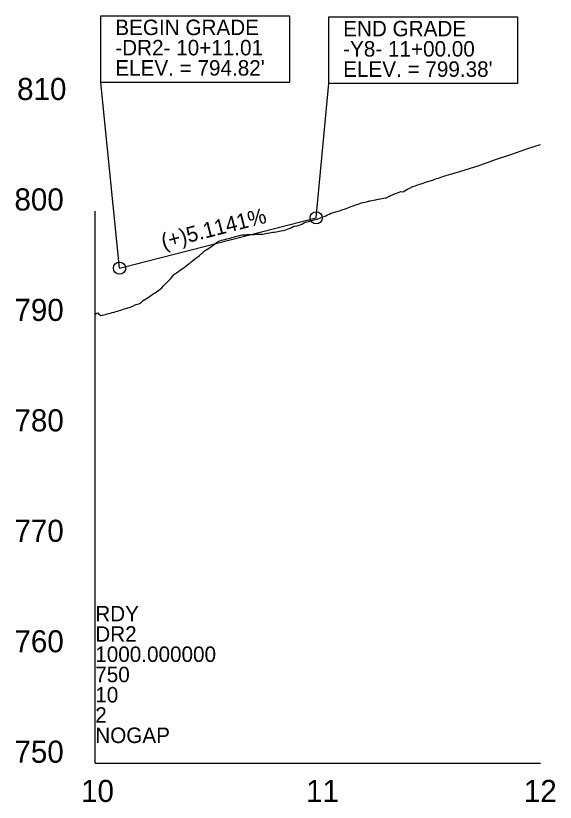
# Model space of a CAD drawing. Extents: x 579185 to 595036, y -53221 to -44640.
# Drawn here: x 593891.4 to 594135.6, y -49552.8 to -49196.7 of the extents above; entities that cross this region are included whole.
import ezdxf

# ---------------------------------------------------------------- set-up
doc = ezdxf.new("R2010")
doc.units = 0
for name, color, linetype in [('Exist Profile Cell', 7, 'Continuous'), ('Exist Vertical Profile Ground Line', 7, 'Continuous'), ('Exist Vertical Profile Horizontal Axis Label Major', 7, 'Continuous'), ('Exist Vertical Profile Vertical Axis Label', 7, 'Continuous'), ('Prop Grid Mask', 7, 'Continuous'), ('Prop Vertical Profile Curve Label', 7, 'Continuous'), ('Prop Vertical Profile Grade', 7, 'Continuous'), ('Prop Vertical Profile Grade Label', 7, 'Continuous'), ('Prop VPI Label', 7, 'Continuous')]:
    doc.layers.add(name, color=color, linetype=linetype)

msp = doc.modelspace()

# ---------------------------------------------------------------- linework, layer by layer
at = {"layer": 'Exist Profile Cell'}
for q in [(593927.42, -49285.12), (594128.93, -49535.12), (593927.42, -49535.12)]:
    msp.add_line((593927.42, -49535.12), q, dxfattribs=at)
at = {"layer": 'Exist Vertical Profile Ground Line'}
for points in [[(594073.42, -49273.27), (594074.19, -49273.01), (594074.96, -49272.76), (594075.74, -49272.49), (594076.51, -49272.23), (594077.28, -49271.98), (594078.05, -49271.73), (594078.83, -49271.48), (594079.6, -49271.24), (594080.55, -49270.96), (594081.14, -49270.74), (594081.92, -49270.46), (594082.69, -49270.19), (594083.46, -49269.93), (594084.23, -49269.67), (594084.67, -49269.52), (594085, -49269.41), (594085.78, -49269.17), (594086.55, -49268.93), (594087.32, -49268.69), (594088.09, -49268.47), (594088.87, -49268.24), (594089.64, -49268.02), (594090.41, -49267.8), (594091.18, -49267.56), (594091.96, -49267.32), (594095.23, -49266.31), (594100.76, -49264.63), (594108.55, -49261.86), (594115.49, -49259.56), (594123.25, -49256.79), (594128.93, -49255.04)], [(594001.58, -49295.59), (594002.35, -49295.56), (594003.12, -49295.53), (594003.89, -49295.5), (594004.67, -49295.35), (594005.44, -49295.15), (594006.21, -49294.98), (594006.98, -49294.86), (594007.76, -49294.75), (594008.53, -49294.63), (594009.3, -49294.5), (594010.07, -49294.37), (594010.85, -49294.24), (594011.62, -49294.12), (594012.39, -49293.99), (594013.16, -49293.86), (594013.94, -49293.53), (594014.71, -49293.21), (594015.66, -49292.81), (594016.25, -49292.54), (594017.03, -49292.2), (594017.4, -49292.04), (594017.8, -49291.95), (594018.57, -49291.77), (594019.34, -49291.6), (594019.73, -49291.52), (594020.12, -49291.34), (594020.89, -49291), (594021.66, -49290.65), (594022.58, -49290.24), (594023.21, -49290.05), (594023.98, -49289.82), (594024.75, -49289.58), (594025.52, -49289.36), (594026.3, -49289.16), (594027.07, -49288.95), (594027.84, -49288.75), (594028.61, -49288.53), (594029.39, -49288.23), (594030.16, -49287.94), (594030.93, -49287.62), (594031.7, -49287.24), (594032.48, -49286.86), (594033.25, -49286.48), (594034.08, -49286.07), (594034.79, -49285.87), (594035.57, -49285.65), (594036.34, -49285.43), (594037.27, -49285.18), (594037.88, -49284.98), (594038.66, -49284.73), (594039.43, -49284.49), (594040.2, -49284.24), (594040.97, -49283.99), (594041.75, -49283.68), (594042.52, -49283.36), (594043.29, -49283.05), (594044.06, -49282.74), (594044.54, -49282.55), (594044.84, -49282.45), (594045.61, -49282.2), (594046.38, -49281.95), (594047.15, -49281.7), (594047.45, -49281.6), (594047.93, -49281.48), (594048.7, -49281.28), (594049.47, -49281.08), (594050.24, -49280.89), (594051.02, -49280.69), (594051.44, -49280.59), (594051.79, -49280.52), (594052.56, -49280.37), (594053.33, -49280.23), (594054.11, -49280.09), (594054.43, -49280.03), (594054.88, -49279.93), (594055.65, -49279.76), (594056.42, -49279.6), (594057.2, -49279.44), (594057.97, -49279.28), (594059, -49279.08), (594059.51, -49278.85), (594060.29, -49278.51), (594061.06, -49278.17), (594062, -49277.77), (594062.6, -49277.52), (594063.38, -49277.2), (594064.15, -49276.89), (594064.92, -49276.58), (594065.69, -49276.35), (594066.75, -49276.38), (594067.24, -49276.11), (594068.01, -49275.69), (594068.78, -49275.26), (594069.56, -49274.85), (594070.33, -49274.43), (594070.74, -49274.21), (594071.1, -49274.08), (594071.87, -49273.81), (594072.65, -49273.54), (594073.42, -49273.27)], [(593927.42, -49331.74), (593928.19, -49331.39), (593928.51, -49331.24), (593928.96, -49331.63), (593929.93, -49332.46), (593930.51, -49332.32), (593931.28, -49332.12), (593932.05, -49331.92), (593932.83, -49331.72), (593933.6, -49331.51), (593934.37, -49331.3), (593935.14, -49331.09), (593935.92, -49330.87), (593936.69, -49330.64), (593937.46, -49330.42), (593938.23, -49330.19), (593939.01, -49329.95), (593939.78, -49329.71), (593940.55, -49329.47), (593941.32, -49329.22), (593942.1, -49328.97), (593942.87, -49328.72), (593943.64, -49328.46), (593944.41, -49328.16), (593945.42, -49327.64), (593945.96, -49327.48), (593946.73, -49327.27), (593947.5, -49326.92), (593948.28, -49326.34), (593949.14, -49325.68), (593949.82, -49325.23), (593950.59, -49324.72), (593951.37, -49324.21), (593952.14, -49323.69), (593952.91, -49323.16), (593953.68, -49322.64), (593954.46, -49322.11), (593955.23, -49321.57), (593956, -49321.03), (593956.77, -49320.49), (593957.55, -49319.85), (593958.32, -49319.05), (593959.09, -49318.23), (593959.86, -49317.42), (593960.64, -49316.59), (593961.41, -49315.77), (593962.18, -49314.93), (593962.95, -49314.08), (593963.4, -49313.54), (593963.73, -49313.37), (593964.19, -49313.12), (593964.5, -49312.9), (593965.27, -49312.34), (593966.04, -49311.79), (593966.81, -49311.22), (593967.59, -49310.66), (593968.36, -49310.09), (593969.13, -49309.52), (593969.9, -49308.94), (593970.25, -49308.68), (593970.68, -49308.34), (593971.45, -49307.71), (593972.22, -49307.08), (593972.99, -49306.45), (593973.77, -49305.82), (593974.54, -49305.18), (593975.31, -49304.53), (593976.08, -49303.85), (593976.86, -49303.19), (593977.63, -49302.75), (593978.4, -49302.3), (593979.17, -49301.85), (593979.95, -49301.22), (593980.72, -49300.59), (593981.49, -49299.96), (593982.26, -49299.33), (593983.33, -49298.71), (593983.81, -49298.58), (593984.58, -49298.37), (593985.35, -49298.17), (593986.13, -49297.96), (593986.9, -49297.75), (593987.67, -49297.55), (593988.44, -49297.34), (593989.22, -49297.13), (593989.99, -49296.92), (593990.76, -49296.72), (593991.53, -49296.51), (593992.31, -49296.3), (593993.08, -49296.09), (593993.85, -49295.89), (593994.84, -49295.86), (593995.4, -49295.83), (593996.17, -49295.8), (593996.94, -49295.77), (593997.71, -49295.74), (593998.49, -49295.71), (593999.26, -49295.68), (594000.03, -49295.65), (594000.8, -49295.62), (594001.58, -49295.59)]]:
    msp.add_lwpolyline(points, dxfattribs=at)
at = {"layer": 'Prop Grid Mask'}
for points in [[(593929.92, -49196.72), (594015.32, -49196.72), (594015.32, -49226.91), (593929.92, -49226.91)], [(594033.05, -49197.27), (594118.44, -49197.27), (594118.44, -49227.46), (594033.05, -49227.46)]]:
    msp.add_lwpolyline(points, close=True, dxfattribs=at)
at = {"layer": 'Prop Vertical Profile Curve Label'}
for p, q in [((593938.43, -49311), (593929.92, -49226.91)), ((594027.42, -49288.24), (594033.05, -49227.46))]:
    msp.add_line(p, q, dxfattribs=at)
at = {"layer": 'Prop Vertical Profile Grade'}
msp.add_line((593938.43, -49311), (594027.42, -49288.24), dxfattribs=at)
at = {"layer": 'Prop VPI Label'}
for centre in [(594027.42, -49288.24), (593938.43, -49311)]:
    msp.add_circle(centre, 2.75, dxfattribs=at)

# ---------------------------------------------------------------- texts
at = {"layer": 'Exist Profile Cell'}
for s, p in [('RDY', (593927.42, -49470.88)), ('DR2', (593927.42, -49480.06)), ('1000.000000', (593927.42, -49489.23)), ('750', (593927.42, -49498.41)), ('10', (593927.42, -49507.59)), ('2', (593927.42, -49516.76)), ('NOGAP', (593927.42, -49525.94))]:
    msp.add_text(s, height=7, dxfattribs=at).set_placement(p)
at = {"layer": 'Exist Vertical Profile Horizontal Axis Label Major'}
for s, p in [('10', (593921, -49552.62)), ('11', (594022.84, -49552.62)), ('12', (594121.39, -49552.62))]:
    msp.add_text(s, height=10, dxfattribs=at).set_placement(p)
at = {"layer": 'Exist Vertical Profile Vertical Axis Label'}
for s, p in [('810', (593892.05, -49234.87)), ('800', (593890.85, -49284.87)), ('790', (593890.85, -49334.87)), ('780', (593890.85, -49384.87)), ('770', (593890.85, -49434.87)), ('760', (593890.85, -49484.87)), ('750', (593890.85, -49534.87))]:
    msp.add_text(s, height=10, dxfattribs=at).set_placement(p)
at = {"layer": 'Prop Vertical Profile Grade Label'}
msp.add_text('(+)5.1141%', height=7, rotation=14.3434, dxfattribs=at).set_placement((593958.27, -49302.41))
at = {"layer": 'Prop VPI Label'}
for s, p in [('BEGIN GRADE', (593936.48, -49205.48)), ('END GRADE', (594039.6, -49206.03)), ('-DR2- 10+11.01', (593936.48, -49214.66)), ('-Y8- 11+00.00', (594039.6, -49215.21)), ("ELEV. = 794.82'", (593936.48, -49223.83)), ("ELEV. = 799.38'", (594039.6, -49224.38))]:
    msp.add_text(s, height=7, dxfattribs=at).set_placement(p)

doc.saveas('drawing.dxf')
